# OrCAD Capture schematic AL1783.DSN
size Custom; title: AL1783,Three-Channel Linear LED Driver; rev: 1.3; note: DS XXXXX Rev. 1- 4
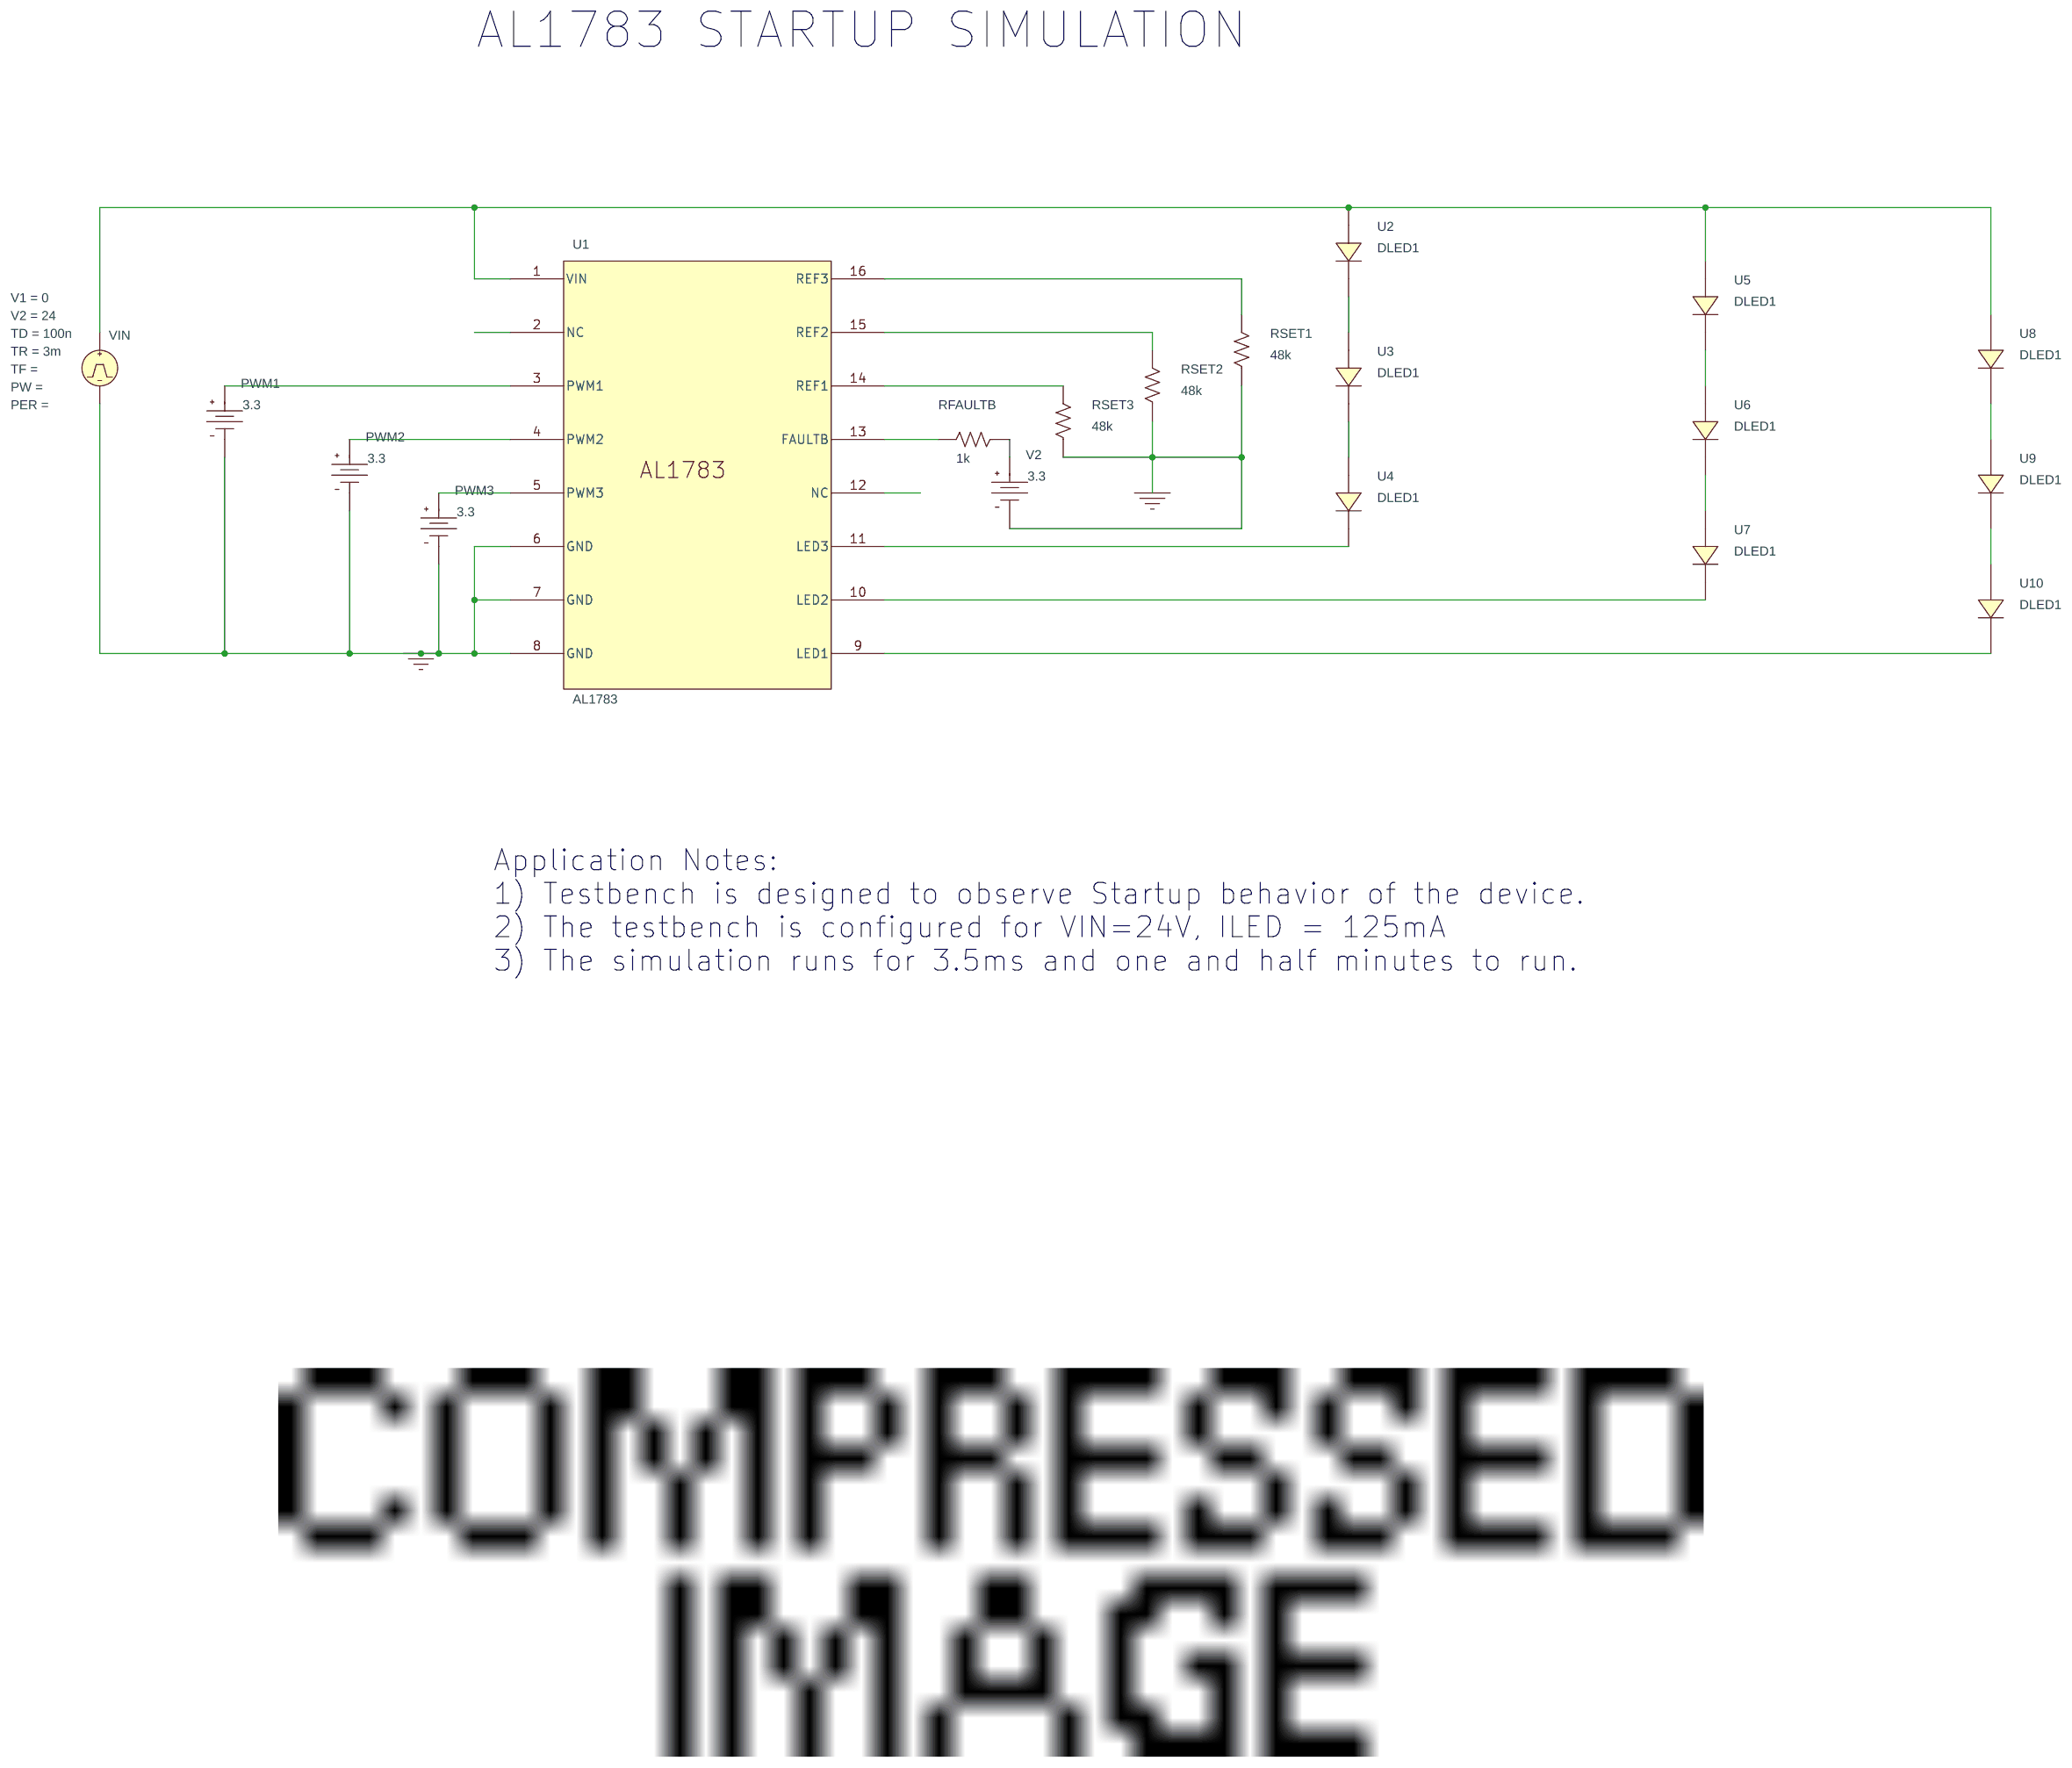
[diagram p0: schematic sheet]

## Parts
PWM1  VDC
PWM2  VDC
PWM3  VDC
RFAULTB  1k  [AX/RC05]
RSET1  48k  [AX/RC05]
RSET2  48k  [AX/RC05]
RSET3  48k  [AX/RC05]
U1  AL1783
U2  DLED1
U3  DLED1
U4  DLED1
U5  DLED1
U6  DLED1
U7  DLED1
U8  DLED1
U9  DLED1
U10  DLED1
V2  VDC
VIN  VPULSE

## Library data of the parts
PWM1-PWM3 V2 = VDC: DC: 3.3
RFAULTB RSET1-RSET3 = R
U1 = AL1783
U2-U10 = DLED1
VIN = VPULSE: TD: 100n; TR: 3m; V1: 0; V2: 24

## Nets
0: PWM1.1(-) PWM2.1(-) PWM3.1(-) RSET1.1 RSET2.1 RSET3.1 U1.6(GND) U1.7(GND) U1.8(GND) V2.1(-) VIN.2(-)
N246910: U6.2 U7.1
N247032: U8.2 U9.1
N247104: U5.2 U6.1
N247154: U2.2 U3.1
N247204: U1.11(LED3) U4.2
N247210: U1.10(LED2) U7.2
N247216: U1.9(LED1) U10.2
N247222: U1.1(VIN) U2.1 U5.1 U8.1 VIN.1(+)
N247322: RSET1.2 U1.16(REF3)
N247328: RSET2.2 U1.15(REF2)
N247334: RSET3.2 U1.14(REF1)
N247378: RFAULTB.2 U1.13(FAULTB)
N247408: RFAULTB.1 V2.0(+)
N247440: PWM1.0(+) U1.3(PWM1)
N247446: PWM3.0(+) U1.5(PWM3)
N247682: U9.2 U10.1
N247686: PWM2.0(+) U1.4(PWM2)
N247794: U3.2 U4.1

Not connected (* = marked no-connect by the designer): U1 2(NC) 12(NC)

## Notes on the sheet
- AL1783 STARTUP SIMULATION
- Application Notes:
  1) Testbench is designed to observe Startup behavior of the device.
  2) The testbench is configured for VIN=24V, ILED = 125mA
  3) The simulation runs for 3.5ms and one and half minutes to run.
